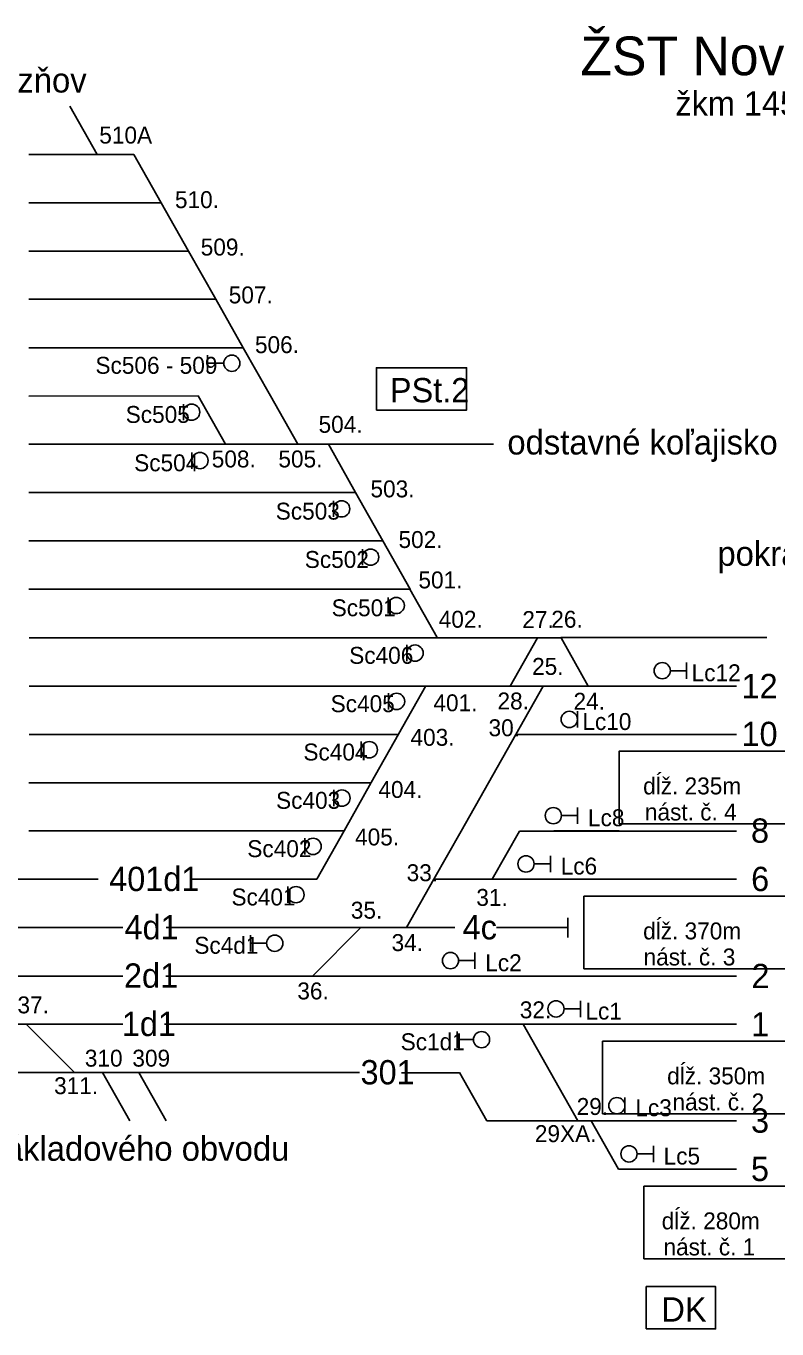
# Model space of a CAD drawing. Extents: x -119 to 851, y -238 to 59.
# Drawn here: x 470.5 to 501.6, y -121.9 to -68 of the extents above; entities that cross this region are included whole.
import ezdxf

# ---------------------------------------------------------------- set-up
doc = ezdxf.new("R2010")
doc.units = 0
for name, color, linetype in [('budova', 7, 'Continuous'), ('Level 2', 7, 'Continuous'), ('nastupistia', 7, 'Continuous'), ('netlač', 7, 'Continuous'), ('popisky stanic a zastavok', 7, 'Continuous'), ('PU_navestidla', 7, 'Continuous'), ('PU_oznacenie navestidiel', 7, 'Continuous'), ('PU_stan_kolaje', 7, 'Continuous'), ('PU_vlecky', 7, 'Continuous')]:
    doc.layers.add(name, color=color, linetype=linetype)

msp = doc.modelspace()

# ---------------------------------------------------------------- linework, layer by layer
at = {"layer": 'budova'}
for points in [[(484.993, -83.903), (488.721, -83.903), (488.721, -82.154), (484.993, -82.154)], [(484.993, -83.903), (488.721, -83.903), (488.721, -82.154), (484.993, -82.154)], [(496.156, -121.9), (499.024, -121.9), (499.024, -120.152), (496.156, -120.152)], [(496.156, -121.9), (499.024, -121.9), (499.024, -120.152), (496.156, -120.152)]]:
    msp.add_lwpolyline(points, close=True, dxfattribs=at)
at = {"layer": 'Level 2'}
for p, q in [((489.829, -85.317), (483.001, -85.317)), ((489.829, -85.317), (483.001, -85.317)), ((495.03, -101.308), (492.33, -101.308)), ((495.03, -101.308), (492.33, -101.308)), ((494.13, -103.307), (488.231, -103.307)), ((494.13, -103.307), (488.231, -103.307)), ((492.915, -105.706), (492.915, -104.906)), ((492.915, -105.706), (492.915, -104.906)), ((486.241, -105.306), (488.236, -105.306)), ((486.241, -105.306), (488.236, -105.306)), ((489.96, -105.306), (492.915, -105.306)), ((489.96, -105.306), (492.915, -105.306)), ((451.932, -107.305), (474.492, -107.305)), ((451.932, -107.305), (474.492, -107.305)), ((476.282, -107.305), (499.894, -107.305)), ((476.282, -107.305), (499.894, -107.305)), ((488.434, -111.303), (486.031, -111.303)), ((488.434, -111.303), (486.031, -111.303))]:
    msp.add_line(p, q, dxfattribs=at)
at = {"layer": 'nastupistia'}
for points in [[(495.035, -101.018), (506.759, -101.018), (506.759, -98.011), (495.035, -98.011)], [(495.035, -101.018), (506.759, -101.018), (506.759, -98.011), (495.035, -98.011)], [(493.579, -107.014), (508.429, -107.014), (508.429, -104.007), (493.579, -104.007)], [(493.579, -107.014), (508.429, -107.014), (508.429, -104.007), (493.579, -104.007)], [(494.349, -113.009), (508.429, -113.009), (508.429, -110.001), (494.349, -110.001)], [(494.349, -113.009), (508.429, -113.009), (508.429, -110.001), (494.349, -110.001)], [(496.059, -119.004), (506.682, -119.004), (506.682, -115.997), (496.059, -115.997)], [(496.059, -119.004), (506.682, -119.004), (506.682, -115.997), (496.059, -115.997)]]:
    msp.add_lwpolyline(points, close=True, dxfattribs=at)
at = {"layer": 'netlač'}
for p, q in [((474.957, -73.327), (470.607, -73.327)), ((476.086, -75.325), (470.607, -75.325)), ((476.086, -75.325), (470.607, -75.325)), ((477.216, -77.324), (470.607, -77.324)), ((477.216, -77.324), (470.607, -77.324)), ((478.346, -79.322), (470.607, -79.322)), ((478.346, -79.322), (470.607, -79.322)), ((479.476, -81.321), (470.607, -81.321)), ((479.476, -81.321), (470.607, -81.321)), ((477.621, -83.319), (470.607, -83.32)), ((477.621, -83.319), (470.607, -83.32)), ((483.001, -85.317), (470.607, -85.317)), ((483.001, -85.317), (470.607, -85.317)), ((484.131, -87.316), (470.607, -87.316)), ((484.131, -87.316), (470.607, -87.316)), ((485.261, -89.314), (470.607, -89.314)), ((485.261, -89.314), (470.607, -89.314)), ((486.391, -91.313), (470.607, -91.313)), ((486.391, -91.313), (470.607, -91.313)), ((492.63, -93.315), (470.624, -93.315)), ((492.63, -93.315), (470.624, -93.315)), ((492.628, -93.312), (501.148, -93.312)), ((492.628, -93.312), (501.148, -93.312)), ((487.04, -95.313), (470.62, -95.313)), ((487.04, -95.313), (470.62, -95.313)), ((487.04, -95.313), (491.891, -95.314)), ((487.04, -95.313), (491.891, -95.314)), ((499.894, -95.314), (491.891, -95.314)), ((499.894, -95.314), (491.891, -95.314)), ((485.91, -97.312), (470.615, -97.312)), ((485.91, -97.312), (470.615, -97.312)), ((499.894, -97.312), (490.761, -97.312)), ((499.894, -97.312), (490.761, -97.312)), ((484.78, -99.31), (470.611, -99.31)), ((484.78, -99.31), (470.611, -99.31)), ((483.65, -101.308), (470.607, -101.308)), ((483.65, -101.308), (470.607, -101.308)), ((499.894, -101.309), (490.905, -101.309)), ((499.894, -101.309), (490.905, -101.309)), ((456.871, -103.307), (473.479, -103.307)), ((456.871, -103.307), (473.479, -103.307)), ((482.52, -103.307), (477.338, -103.307)), ((482.52, -103.307), (477.338, -103.307)), ((487.371, -103.307), (499.894, -103.307)), ((487.371, -103.307), (499.894, -103.307)), ((474.492, -105.306), (451.932, -105.306)), ((474.492, -105.306), (451.932, -105.306)), ((486.241, -105.306), (476.286, -105.306)), ((486.241, -105.306), (476.286, -105.306)), ((463.603, -109.302), (474.492, -109.302)), ((463.603, -109.302), (474.492, -109.302)), ((499.894, -109.302), (476.215, -109.302)), ((499.894, -109.302), (476.215, -109.302)), ((484.296, -111.301), (452.322, -111.301)), ((484.296, -111.301), (452.322, -111.301)), ((493.323, -113.3), (489.563, -113.3)), ((493.323, -113.3), (489.563, -113.3)), ((499.894, -113.3), (493.323, -113.3)), ((499.894, -113.3), (493.323, -113.3)), ((499.894, -115.298), (495.005, -115.298)), ((499.894, -115.298), (495.005, -115.298))]:
    msp.add_line(p, q, dxfattribs=at)
at = {"layer": 'PU_navestidla'}
for p, q in [((478, -82.301), (478, -81.629)), ((478, -82.301), (478, -81.629)), ((478, -81.964), (478.672, -81.964)), ((478, -81.964), (478.672, -81.964)), ((477.007, -84.324), (477.007, -83.652)), ((477.007, -84.324), (477.007, -83.652)), ((477.355, -86.325), (477.355, -85.653)), ((477.355, -86.325), (477.355, -85.653)), ((483.214, -88.323), (483.214, -87.651)), ((483.214, -88.323), (483.214, -87.651)), ((484.414, -90.321), (484.414, -89.649)), ((484.414, -90.321), (484.414, -89.649)), ((485.474, -92.32), (485.474, -91.648)), ((485.474, -92.32), (485.474, -91.648)), ((486.254, -94.287), (486.254, -93.615)), ((486.254, -94.287), (486.254, -93.615)), ((497.827, -94.679), (497.155, -94.679)), ((497.827, -94.679), (497.155, -94.679)), ((497.827, -94.341), (497.827, -95.013)), ((497.827, -94.341), (497.827, -95.013)), ((485.489, -96.285), (485.489, -95.613)), ((485.489, -96.285), (485.489, -95.613)), ((493.308, -96.358), (493.308, -97.03)), ((493.308, -96.358), (493.308, -97.03)), ((484.359, -98.284), (484.359, -97.612)), ((484.359, -98.284), (484.359, -97.612)), ((483.229, -100.283), (483.229, -99.611)), ((483.229, -100.283), (483.229, -99.611)), ((493.318, -100.674), (492.646, -100.674)), ((493.318, -100.674), (492.646, -100.674)), ((493.318, -100.337), (493.318, -101.009)), ((493.318, -100.337), (493.318, -101.009)), ((482.035, -102.281), (482.035, -101.609)), ((482.035, -102.281), (482.035, -101.609)), ((492.188, -102.335), (492.188, -103.007)), ((492.188, -102.335), (492.188, -103.007)), ((492.188, -102.673), (491.516, -102.673)), ((492.188, -102.673), (491.516, -102.673)), ((481.327, -104.279), (481.327, -103.607)), ((481.327, -104.279), (481.327, -103.607)), ((479.775, -106.287), (479.775, -105.615)), ((479.775, -106.287), (479.775, -105.615)), ((479.775, -105.949), (480.447, -105.949)), ((479.775, -105.949), (480.447, -105.949)), ((489.064, -106.67), (488.392, -106.67)), ((489.064, -106.67), (488.392, -106.67)), ((489.064, -106.333), (489.064, -107.005)), ((489.064, -106.333), (489.064, -107.005)), ((493.431, -108.668), (492.759, -108.668)), ((493.431, -108.668), (492.759, -108.668)), ((493.431, -108.331), (493.431, -109.002)), ((493.431, -108.331), (493.431, -109.002)), ((488.333, -110.275), (488.333, -109.603)), ((488.333, -110.275), (488.333, -109.603)), ((488.333, -109.937), (489.005, -109.937)), ((488.333, -109.937), (489.005, -109.937)), ((495.277, -112.33), (495.277, -113.002)), ((495.277, -112.33), (495.277, -113.002)), ((496.45, -114.663), (495.778, -114.663)), ((496.45, -114.663), (495.778, -114.663)), ((496.45, -114.326), (496.45, -114.998)), ((496.45, -114.326), (496.45, -114.998))]:
    msp.add_line(p, q, dxfattribs=at)
for centre in [(479.008, -81.965), (479.008, -81.965), (477.343, -83.988), (477.343, -83.988), (477.691, -85.989), (477.691, -85.989), (483.55, -87.987), (483.55, -87.987), (484.75, -89.985), (484.75, -89.985), (485.81, -91.984), (485.81, -91.984), (486.59, -93.951), (486.59, -93.951), (496.819, -94.677), (496.819, -94.677), (485.825, -95.949), (485.825, -95.949), (492.972, -96.694), (492.972, -96.694), (484.695, -97.948), (484.695, -97.948), (483.565, -99.947), (483.565, -99.947), (492.31, -100.673), (492.31, -100.673), (482.371, -101.945), (482.371, -101.945), (491.18, -102.671), (491.18, -102.671), (481.663, -103.943), (481.663, -103.943), (480.783, -105.951), (480.783, -105.951), (488.056, -106.669), (488.056, -106.669), (492.423, -108.666), (492.423, -108.666), (489.341, -109.939), (489.341, -109.939), (494.941, -112.666), (494.941, -112.666), (495.442, -114.662), (495.442, -114.662)]:
    msp.add_circle(centre, 0.336, dxfattribs=at)
at = {"layer": 'PU_stan_kolaje'}
for points in [[(472.305, -71.328), (473.435, -73.327)], [(474.957, -73.327), (476.086, -75.325)], [(474.957, -73.327), (476.086, -75.325)], [(476.086, -75.325), (477.216, -77.324)], [(476.086, -75.325), (477.216, -77.324)], [(477.216, -77.324), (478.346, -79.322)], [(477.216, -77.324), (478.346, -79.322)], [(478.346, -79.322), (479.476, -81.321)], [(478.346, -79.322), (479.476, -81.321)], [(479.476, -81.321), (480.606, -83.319)], [(479.476, -81.321), (480.606, -83.319)], [(477.621, -83.319), (478.751, -85.317)], [(477.621, -83.319), (478.751, -85.317)], [(480.606, -83.319), (481.736, -85.317)], [(480.606, -83.319), (481.736, -85.317)], [(483.001, -85.317), (484.131, -87.316)], [(483.001, -85.317), (484.131, -87.316)], [(484.131, -87.316), (485.261, -89.314)], [(484.131, -87.316), (485.261, -89.314)], [(485.261, -89.314), (486.391, -91.313)], [(485.261, -89.314), (486.391, -91.313)], [(486.372, -91.313), (487.502, -93.312)], [(486.372, -91.313), (487.502, -93.312)], [(490.531, -95.314), (491.661, -93.315)], [(490.531, -95.314), (491.661, -93.315)], [(492.63, -93.315), (493.76, -95.314)], [(492.63, -93.315), (493.76, -95.314)], [(485.91, -97.311), (487.04, -95.312)], [(485.91, -97.311), (487.04, -95.312)], [(490.761, -97.312), (491.891, -95.314)], [(490.761, -97.312), (491.891, -95.314)], [(484.78, -99.309), (485.91, -97.311)], [(484.78, -99.309), (485.91, -97.311)], [(489.631, -99.31), (490.761, -97.312)], [(489.631, -99.31), (490.761, -97.312)], [(483.65, -101.308), (484.78, -99.309)], [(483.65, -101.308), (484.78, -99.309)], [(488.501, -101.309), (489.631, -99.31)], [(488.501, -101.309), (489.631, -99.31)], [(482.52, -103.306), (483.65, -101.308)], [(482.52, -103.306), (483.65, -101.308)], [(487.371, -103.307), (488.501, -101.309)], [(487.371, -103.307), (488.501, -101.309)], [(489.775, -103.307), (490.905, -101.309)], [(489.775, -103.307), (490.905, -101.309)], [(486.241, -105.306), (487.371, -103.307)], [(486.241, -105.306), (487.371, -103.307)], [(484.339, -105.306), (482.34, -107.305)], [(484.339, -105.306), (482.34, -107.305)], [(470.497, -109.302), (472.496, -111.301)], [(470.497, -109.302), (472.496, -111.301)], [(491.063, -109.302), (492.193, -111.301)], [(491.063, -109.302), (492.193, -111.301)], [(473.655, -111.301), (474.785, -113.299)], [(473.655, -111.301), (474.785, -113.299)], [(475.158, -111.301), (476.288, -113.299)], [(475.158, -111.301), (476.288, -113.299)], [(488.433, -111.301), (489.563, -113.299)], [(488.433, -111.301), (489.563, -113.299)], [(492.193, -111.301), (493.323, -113.299)], [(492.193, -111.301), (493.323, -113.299)], [(493.875, -113.299), (495.005, -115.298)], [(493.875, -113.299), (495.005, -115.298)]]:
    msp.add_lwpolyline(points, dxfattribs=at)

# ---------------------------------------------------------------- texts
at = {"layer": 'budova'}
for s, p in [('PSt.2', (485.549, -83.581)), ('PSt.2', (485.549, -83.581)), ('DK', (496.786, -121.596)), ('DK', (496.786, -121.596))]:
    msp.add_text(s, height=1.0044, dxfattribs=at).set_placement(p)
at = {"layer": 'nastupistia'}
for s, p in [('dĺž. 235m', (496.027, -99.795)), ('dĺž. 235m', (496.027, -99.795)), ('nást. č. 4', (496.101, -100.872)), ('nást. č. 4', (496.101, -100.872)), ('dĺž. 370m', (496.027, -105.791)), ('dĺž. 370m', (496.027, -105.791)), ('nást. č. 3', (496.046, -106.868)), ('nást. č. 3', (496.046, -106.868)), ('dĺž. 350m', (497.021, -111.785)), ('dĺž. 350m', (497.021, -111.785)), ('nást. č. 2', (497.242, -112.863)), ('nást. č. 2', (497.242, -112.863)), ('dĺž. 280m', (496.796, -117.781)), ('dĺž. 280m', (496.796, -117.781)), ('nást. č. 1', (496.87, -118.858)), ('nást. č. 1', (496.87, -118.858))]:
    msp.add_text(s, height=0.7, dxfattribs=at).set_placement(p)
at = {"layer": 'popisky stanic a zastavok'}
for s, height, p in [('ŽST Nové Zámky', 1.6, (493.433, -70.054)), ('žkm 145,385', 1.00438, (497.364, -71.722))]:
    msp.add_text(s, height=height, dxfattribs=at).set_placement(p)
at = {"layer": 'PU_oznacenie navestidiel'}
for s, p in [('510A', (473.523, -72.881)), ('510.', (476.653, -75.55)), ('510.', (476.653, -75.55)), ('509.', (477.719, -77.511)), ('509.', (477.719, -77.511)), ('507.', (478.879, -79.49)), ('507.', (478.879, -79.49)), ('506.', (479.964, -81.546)), ('506.', (479.964, -81.546)), ('Sc506 - 509', (473.363, -82.401)), ('Sc506 - 509', (473.363, -82.401)), ('Sc505', (474.615, -84.433)), ('Sc505', (474.615, -84.433)), ('504.', (482.597, -84.842)), ('504.', (482.597, -84.842)), ('508.', (478.175, -86.274)), ('508.', (478.175, -86.274)), ('505.', (480.934, -86.274)), ('505.', (480.934, -86.274)), ('Sc504', (474.966, -86.433)), ('Sc504', (474.966, -86.433)), ('503.', (484.745, -87.511)), ('503.', (484.745, -87.511)), ('Sc503', (480.824, -88.432)), ('Sc503', (480.824, -88.432)), ('502.', (485.906, -89.605)), ('502.', (485.906, -89.605)), ('Sc502', (482.026, -90.43)), ('Sc502', (482.026, -90.43)), ('501.', (486.729, -91.275)), ('501.', (486.729, -91.275)), ('Sc501', (483.139, -92.429)), ('Sc501', (483.139, -92.429)), ('402.', (487.569, -92.902)), ('402.', (487.569, -92.902)), ('27.', (491.029, -92.914)), ('27.', (491.029, -92.914)), ('26.', (492.227, -92.902)), ('26.', (492.227, -92.902)), ('Sc406', (483.864, -94.395)), ('Sc406', (483.864, -94.395)), ('25.', (491.433, -94.852)), ('25.', (491.433, -94.852)), ('Lc12', (498.034, -95.116)), ('Lc12', (498.034, -95.116)), ('Sc405', (483.096, -96.394)), ('Sc405', (483.096, -96.394)), ('401.', (487.349, -96.357)), ('401.', (487.349, -96.357)), ('28.', (490.001, -96.282)), ('28.', (490.001, -96.282)), ('24.', (493.148, -96.294)), ('24.', (493.148, -96.294)), ('Lc10', (493.513, -97.132)), ('Lc10', (493.513, -97.132)), ('30.', (489.632, -97.389)), ('30.', (489.632, -97.389)), ('403.', (486.401, -97.785)), ('403.', (486.401, -97.785)), ('Sc404', (481.969, -98.392)), ('Sc404', (481.969, -98.392)), ('404.', (485.072, -99.941)), ('404.', (485.072, -99.941)), ('Sc403', (480.839, -100.391)), ('Sc403', (480.839, -100.391)), ('Lc8', (493.745, -101.111)), ('Lc8', (493.745, -101.111)), ('405.', (484.107, -101.906)), ('405.', (484.107, -101.906)), ('Sc402', (479.647, -102.389)), ('Sc402', (479.647, -102.389)), ('33.', (486.242, -103.384)), ('33.', (486.242, -103.384)), ('Lc6', (492.616, -103.109)), ('Lc6', (492.616, -103.109)), ('Sc401', (478.992, -104.388)), ('Sc401', (478.992, -104.388)), ('31.', (489.125, -104.405)), ('31.', (489.125, -104.405)), ('35.', (483.932, -104.933)), ('35.', (483.932, -104.933)), ('34.', (485.619, -106.274)), ('34.', (485.619, -106.274)), ('Sc4d1', (477.456, -106.386)), ('Sc4d1', (477.456, -106.386)), ('Lc2', (489.494, -107.107)), ('Lc2', (489.494, -107.107)), ('36.', (481.718, -108.273)), ('36.', (481.718, -108.273)), ('37.', (470.137, -108.85)), ('37.', (470.137, -108.85)), ('32.', (490.924, -109.054)), ('32.', (490.924, -109.054)), ('Lc1', (493.64, -109.105)), ('Lc1', (493.64, -109.105)), ('Sc1d1', (485.994, -110.374)), ('Sc1d1', (485.994, -110.374)), ('310', (472.925, -111.053)), ('310', (472.925, -111.053)), ('309', (474.891, -111.053)), ('309', (474.891, -111.053)), ('311.', (471.653, -112.191)), ('311.', (471.653, -112.191)), ('29.', (493.278, -113.051)), ('29.', (493.278, -113.051)), ('Lc3', (495.705, -113.104)), ('Lc3', (495.705, -113.104)), ('29XA.', (491.547, -114.174)), ('29XA.', (491.547, -114.174)), ('Lc5', (496.875, -115.1)), ('Lc5', (496.875, -115.1))]:
    msp.add_text(s, height=0.7, dxfattribs=at).set_placement(p)
at = {"layer": 'PU_stan_kolaje'}
for s, height, p in [('12', 1.0044, (500.099, -95.816)), ('12', 1.0044, (500.099, -95.816)), ('10', 1.0044, (500.097, -97.797)), ('10', 1.0044, (500.097, -97.797)), ('8', 1.004, (500.491, -101.794)), ('8', 1.004, (500.491, -101.794)), ('401d1', 1.0044, (473.931, -103.793)), ('401d1', 1.0044, (473.931, -103.793)), ('6', 1.004, (500.497, -103.793)), ('6', 1.004, (500.497, -103.793)), ('4d1', 1.0044, (474.567, -105.791)), ('4d1', 1.0044, (474.567, -105.791)), ('4c', 1.0044, (488.558, -105.791)), ('4c', 1.0044, (488.558, -105.791)), ('2d1', 1.0044, (474.544, -107.789)), ('2d1', 1.0044, (474.544, -107.789)), ('2', 1.004, (500.51, -107.807)), ('2', 1.004, (500.51, -107.807)), ('1d1', 1.0044, (474.453, -109.787)), ('1d1', 1.0044, (474.453, -109.787)), ('1', 1.004, (500.495, -109.805)), ('1', 1.004, (500.495, -109.805)), ('301', 1.0044, (484.334, -111.787)), ('301', 1.0044, (484.334, -111.787)), ('3', 1.004, (500.493, -113.785)), ('3', 1.004, (500.493, -113.785)), ('5', 1.004, (500.489, -115.783)), ('5', 1.004, (500.489, -115.783))]:
    msp.add_text(s, height=height, dxfattribs=at).set_placement(p)
at = {"layer": 'PU_vlecky'}
for s, p in [('opravovňa vozňov', (461.984, -70.77)), ('odstavné koľajisko', (490.41, -85.739)), ('odstavné koľajisko', (490.41, -85.739)), ('pokračovanie odstavného koľajiska', (499.102, -90.343)), ('pokračovanie odstavného koľajiska', (499.102, -90.343)), ('pokračovanie nákladového obvodu', (460.408, -114.947)), ('pokračovanie nákladového obvodu', (460.408, -114.947))]:
    msp.add_text(s, height=1.015, dxfattribs=at).set_placement(p)

doc.saveas('drawing.dxf')
